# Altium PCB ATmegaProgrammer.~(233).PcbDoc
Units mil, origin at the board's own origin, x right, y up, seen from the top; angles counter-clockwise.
Board outline 2130 x 2300 mil, 2 copper layers (Top Layer, Bottom Layer); 13 components, 10 nets, 72 pads, 1 vias.
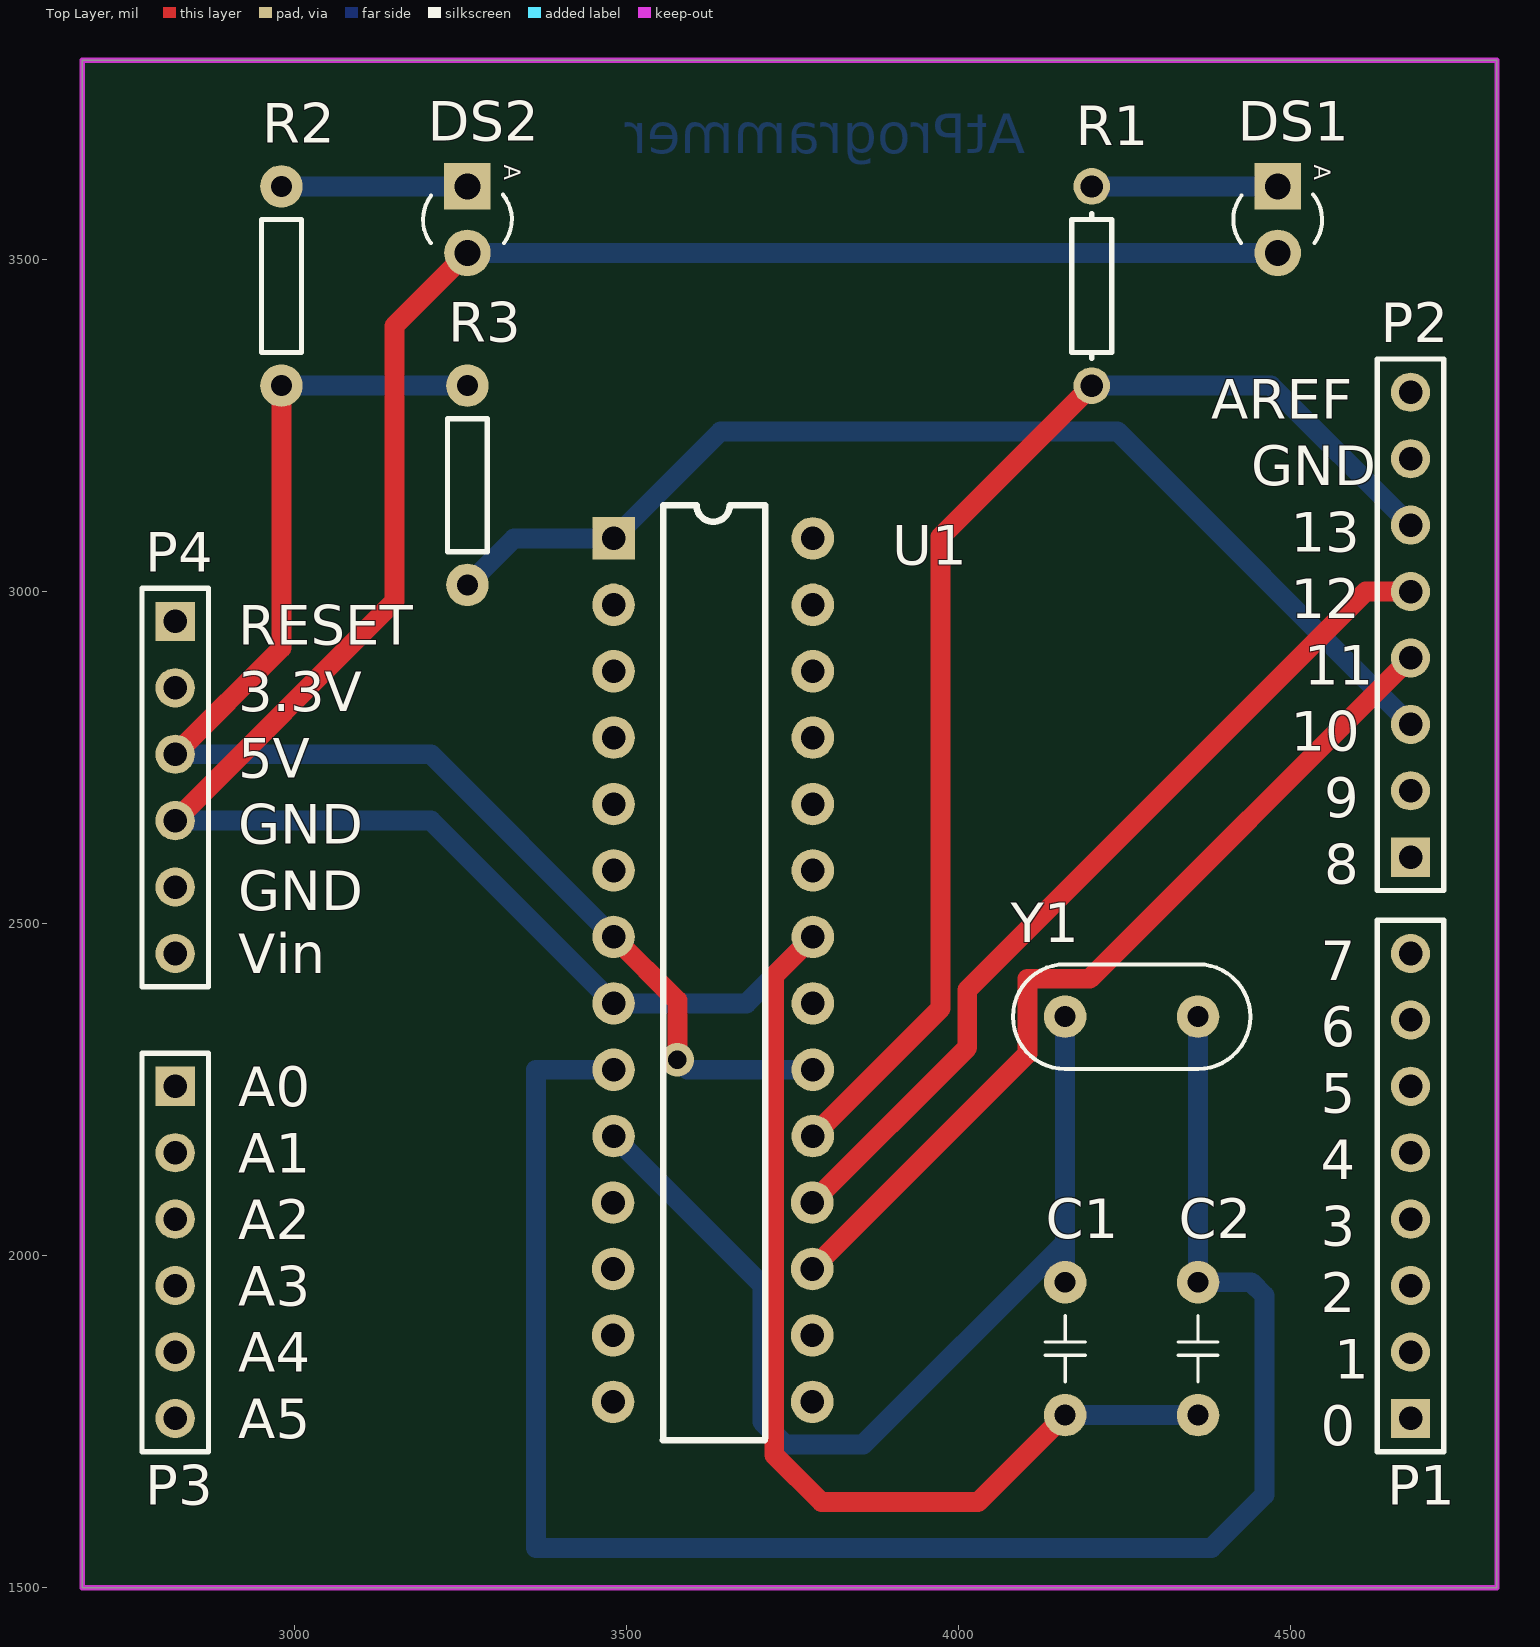
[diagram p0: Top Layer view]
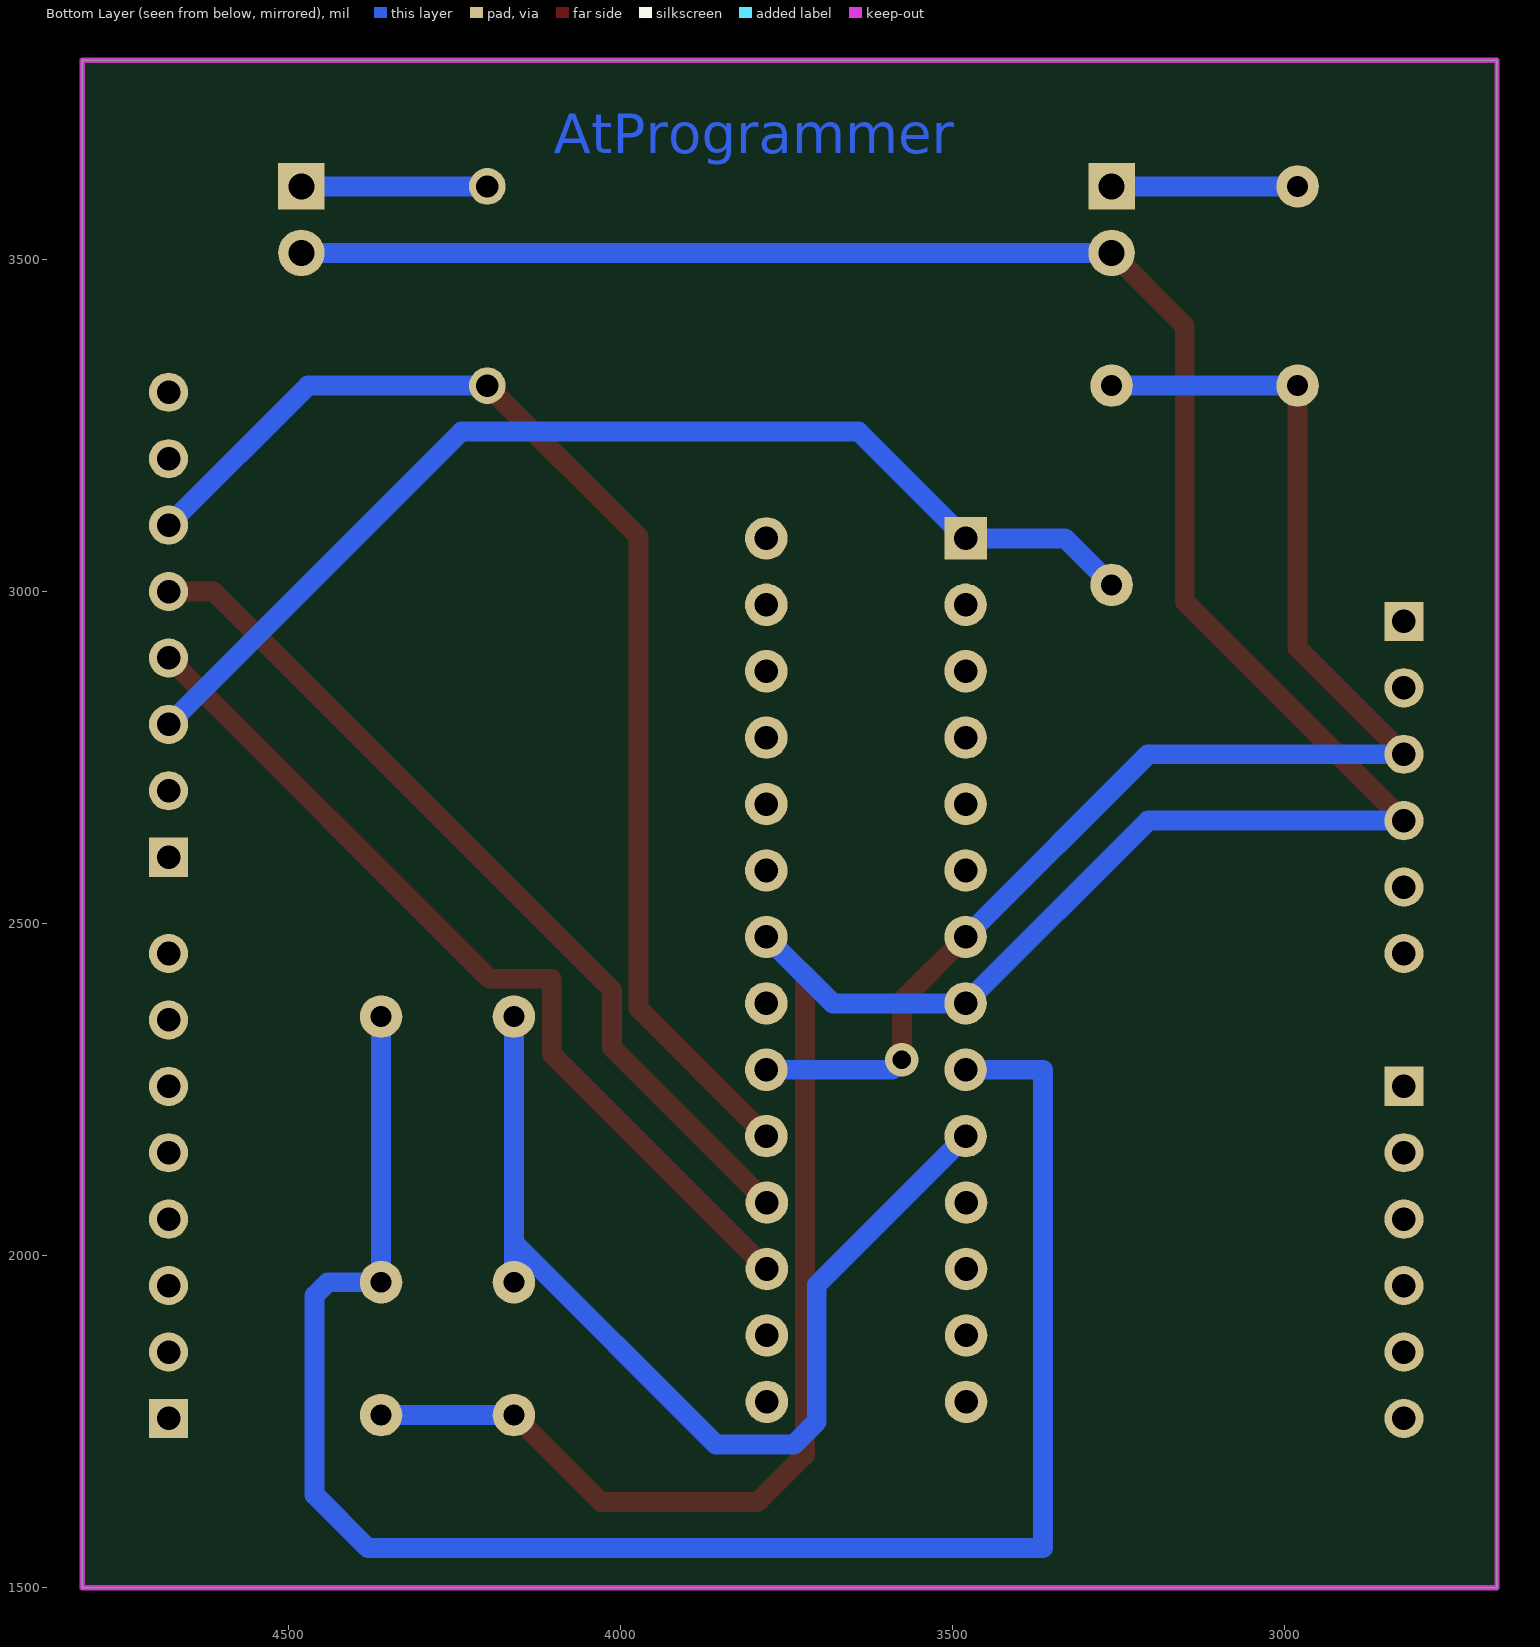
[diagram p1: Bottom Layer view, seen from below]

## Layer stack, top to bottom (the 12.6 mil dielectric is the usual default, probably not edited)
Top Layer: signal copper 1.4
Dielectric: dielectric 12.6, FR-4, Dk 4.8
Bottom Layer: signal copper 1.4

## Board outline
2680,1500 2680,3800 4810,3800 4810,1500

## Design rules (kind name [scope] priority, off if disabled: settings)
Clearance [All] p1: gap=10
PolygonConnect [All] p1: connectstyle=Relief reliefconductorwidth=10 reliefentries=4 polygonreliefangle="90 Angle"
RoutingVias [All] p1: holewidth=28 width=50 viastyle="Through Hole" minholewidth=28 minwidth=50 maxholewidth=28 maxwidth=50
SilkscreenOverComponentPads [All] p1: minsilkscreentomaskgap=10
SolderMaskExpansion [All] p1: expansion=4
Width VCC [All] p1: maxlimit=40 minlimit=20 preferedwidth=30
Width GND [InNet('GND')] p2: maxlimit=40 minlimit=20 preferedwidth=30
Width [All] p3: maxlimit=30 minlimit=10 preferedwidth=20
27 further rules are at their usual default settings.

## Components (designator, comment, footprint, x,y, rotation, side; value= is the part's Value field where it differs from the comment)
C1 "20pF" C200 4160,1860 r180 top
C2 "20pF" C200 4360,1860 r180 top
DS1 "LED" LED-3mm_G 4480,3560 r270 top
DS2 "LED" LED-3mm_G 3260,3560 r270 top
P1 "Header 8" HDR1X8 4680,1755 r90 top
P2 "Header 8" HDR1X8 4680,2600 r90 top
P3 "Header 6" HDR1X6 2820,2255 r270 top
P4 "Header 6" HDR1X6 2820,2955 r270 top
R1 "Res1" AXIAL-0.3#1 4200,3460 r270 top
R2 "220" AXIAL-0.3#2 2980,3460 r270 top
R3 "10k" AXIAL-0.3#2 3260,3160 r90 top
U1 "ATmega328" DIP-28 3480,3080 r270 top
Y1 "16MHz" XTAL4-8 4260,2360 r180 top

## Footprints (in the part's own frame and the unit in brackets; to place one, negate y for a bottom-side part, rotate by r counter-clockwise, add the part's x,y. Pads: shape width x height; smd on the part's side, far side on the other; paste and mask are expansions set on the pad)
AXIAL-0.3#1 [mm] "Axial Device, Thru-Hole; 2 Leads; 0.3 in Pin Spacing"
  round 1.4 hole 0.85: 1(-3.81,0) 2(3.81,0)
  silkscreen extent -2.77,-0.76 2.77,0.76
AXIAL-0.3#2 [mm] "0.3\" Resistor; 2 Leads"
  round 1.626 hole 0.8: 1(-3.81,0) 2(3.81,0)
  silkscreen extent -2.54,-0.76 2.54,0.76, body extent -4.1,-1 4.19,1, height 2.19
C200 [mil] "鹅溅筿甧竟"
  round 64 hole 31.5: 1(0,100) 2(0,-100)
  silkscreen extent -30,-50 30,50, body extent -41,-136 39,135, height 354
DIP-28 [mil]
  rect 64x64 hole 35.43: 1(0,0)
  round 64 hole 35.43: 2(100,0) 3(200,0) 4(300,0) 5(400,0) 6(500,0) 7(600,0) 8(700,0) 9(800,0) 10(900,0) 11(1000,-0.79) 12(1100,-0.79) 13(1200,-0.79) 14(1300,-0.79) 15(1300,299.21) 16(1200,299.21) 17(1100,299.21) 18(1000,299.21) 19(900,300) 20(800,300) 21(700,300) 22(600,300) 23(500,300) 24(400,300) 25(300,300) 26(200,300) 27(100,300) 28(0,300)
  silkscreen extent -50,74 1358,228, body extent -53,-5 1358,304, height 209
HDR1X6 [mm] "Connector; Header; 6 Position"
  rect 1.5x1.5 hole 0.9: 1(0,0)
  round 1.5 hole 0.9: 2(2.54,0) 3(5.08,0) 4(7.62,0) 5(10.16,0) 6(12.7,0)
  silkscreen extent -1.27,-1.27 13.97,1.27
HDR1X8 [mm] "Connector; Header; 8 Position"
  rect 1.5x1.5 hole 0.9: 1(0,0)
  round 1.5 hole 0.9: 2(2.54,0) 3(5.08,0) 4(7.62,0) 5(10.16,0) 6(12.7,0) 7(15.24,0) 8(17.78,0)
  silkscreen extent -1.27,-1.27 19.05,1.27
LED-3mm_G [mil] "3mm LED_Green"
  rect 70x70 hole 39: 1(-50,0)
  round 70 hole 39: 2(50,0)
  silkscreen extent -38,-67 35,67, body extent -66,-68 67,66, height 181
XTAL4-8 [mil]
  round 64 hole 31.5: 1(-100,0) 2(100,0)
  silkscreen extent -179,-79 179,79, body extent -178,-80 192,79, height 157

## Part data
C1 C2: library part Cap, "Capacitor"
DS1 DS2: "Typical INFRARED GaAs LED"
P1 P2: "Header, 8-Pin"
P3 P4: "Header, 6-Pin"
R1: "Resistor"
R2 R3: library part Res, "Resistor"
U1: "Arduino"
Y1: library part XTAL, "Crystal Oscillator"

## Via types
v1: diameter 50, hole 28, Top Layer to Bottom Layer, 1 vias

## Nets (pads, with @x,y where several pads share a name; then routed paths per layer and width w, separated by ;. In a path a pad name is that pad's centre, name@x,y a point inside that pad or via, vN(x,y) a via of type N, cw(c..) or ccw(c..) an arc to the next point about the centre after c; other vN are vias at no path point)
GND: C1.1 C2.1 DS1.2 DS2.2 P4.4 U1.8 U1.22 | length 4898.3
  Top Layer w30: P4.4 3150,2985 3150,3400 DS2.2 ; U1.22 3722,2422 3722,1700 3793,1629 4029,1629 C1.1
  Bottom Layer w30: P4.4 3205,2655 U1.8 3680,2380 U1.22 ; DS2.2 DS1.2 ; C1.1 C2.1
MISO: P2.5 U1.18 | length 1332.7
  Top Layer w30: U1.18 4012.5,2313.29 4012.5,2400 4612.5,3000 P2.5
MOSI: P2.4 U1.17 | length 1348.2
  Top Layer w30: U1.17 4103,2303.79 4103,2417 4197,2417 P2.4
NetC1_2: C1.2 U1.10 Y1.2 | length 1858.8
  Bottom Layer w30: U1.10 3704,1956 3704,1750 3738,1716 3856,1716 4160,2020 Y1.2 C1.2
NetC2_2: C2.2 U1.9 Y1.1 | length 2831.1
  Bottom Layer w30: 3363.43,2256.57 3363.43,2200 ; U1.9 3363.43,2280 3363.43,2200 ; Y1.1 C2.2 4440,1960 4460,1940 4460,1640 4380,1560 3363.43,1560 3363.43,2200
NetDS1_1: DS1.1 R1.1 | length 280
  Bottom Layer w30: R1.1 DS1.1
NetDS2_1: DS2.1 R2.1 | length 280
  Bottom Layer w30: R2.1 DS2.1
RESET: P2.3 R3.1 U1.1 | length 1698.4
  Bottom Layer w30: R3.1 3330,3080 U1.1 3641,3241 4239,3241 P2.3
SCK: P2.6 R1.2 U1.19 | length 1871
  Top Layer w30: U1.19 3972.5,2372.5 3972.5,3082.5 R1.2
  Bottom Layer w30: R1.2 4470,3310 P2.6
VCC: P4.3 R2.2 R3.2 U1.7 U1.20 | length 2110.2
  Top Layer w30: P4.3 2980,2915 R2.2 ; U1.7 3576,2384 v1(3576,2295)
  Bottom Layer w30: P4.3 3205,2755 U1.7 ; R2.2 R3.2 ; v1(3576,2295) 3591,2280 U1.20
pads on no net: P1.1 P1.2 P1.3 P1.4 P1.5 P1.6 P1.7 P1.8 P2.1 P2.2 P2.7 P2.8 P3.1 P3.2 P3.3 P3.4 P3.5 P3.6 P4.1 P4.2 P4.5 P4.6 U1.2 U1.3 U1.4 U1.5 U1.6 U1.11 U1.12 U1.13 U1.14 U1.15 U1.16 U1.21 U1.23 U1.24 U1.25 U1.26 U1.27 U1.28

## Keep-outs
Keep-Out Layer:
  the board outline again, w7.87

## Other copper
Bottom Layer:
  text "AtProgrammer" at 4100,3660 h60

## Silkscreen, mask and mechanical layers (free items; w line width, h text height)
Top Overlay:
  lines w7.87: 0,0 0,200 ; 20,0 35,0 ; 55,0 195,0 ; 2770,2246.75 2770,2255
  text "AREF" at 4380.02,3260 h60
  text "GND" at 4440,3160 h60
  text "13" at 4499.96,3060 h60
  text "12" at 4499.96,2960 h60
  text "RESET" at 2915.05,2920 h60
  text "11" at 4519.95,2860 h60
  text "3.3V" at 2915.05,2820 h60
  text "10" at 4499.96,2760 h60
  text "5V" at 2915.05,2720 h60
  text "9" at 4549.94,2660 h60
  text "GND" at 2915.05,2620 h60
  text "8" at 4549.94,2560 h60
  text "GND" at 2915.05,2520 h60
  text "Vin" at 2915.05,2425 h60
  text "7" at 4544.94,2415 h60
  text "6" at 4544.94,2315 h60
  text "A0" at 2915.05,2225 h60
  text "5" at 4544.94,2215 h60
  text "A1" at 2915.05,2125 h60
  text "4" at 4544.94,2115 h60
  text "A2" at 2915.05,2025 h60
  text "3" at 4544.94,2015 h60
  text "A3" at 2915.05,1925 h60
  text "2" at 4544.94,1915 h60
  text "A4" at 2915.05,1825 h60
  text "1" at 4564.94,1815 h60
  text "A5" at 2915.05,1725 h60
  text "0" at 4544.94,1715 h60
